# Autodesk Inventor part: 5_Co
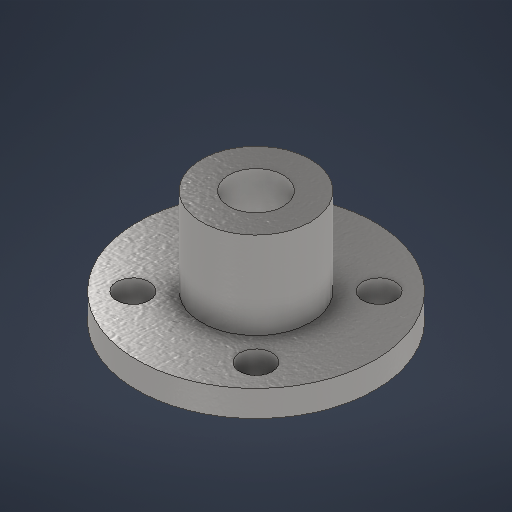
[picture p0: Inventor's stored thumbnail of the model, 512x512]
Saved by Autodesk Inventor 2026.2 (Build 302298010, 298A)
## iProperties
Created: 2026-03
Part Number: 5_Co
Material: 스테인리스스틸
Document SubType Name: Modeling
Designer: work
Density: 8 g/cm^3
Appearance: 아연도금
Mass: 10.0186 g
Surface Area: 13.3747 cm^2
Volume: 1.25232 cm^3
Author: work
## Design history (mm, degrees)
sketch "스케치1"
  geometry: L1 (0, 0)-(0, 10.4); L2 (2.5, 0)-(2.5, 10.4); L3 (2.5, 10.4)-(5, 10.4); L4 (5, 10.4)-(5, 2.4); L5 (5, 2.4)-(10.95, 2.4); L6 (10.95, 2.4)-(10.95, 0); L7 (2.5, 0)-(10.95, 0); L8 (2.5, 0)-(0, 0); 1 further point
  constraints: 16 end point, 6 perpendicular, 2 vertical, 1 midpoint
  dimensions: "d0" = 10.4 distance of L1.start L1.end; "d1" = 2.4 distance between parallel lines of L5 L7; "d2" = 10 diameter of L4 L1; "d3" = 5 diameter of L2 L1; "d4" = 10.4 distance from line of L1.start L3; "d5" = 21.9 diameter of point (10.95, 1.2) L1
revolve "회전1" sketch "스케치1" stored, may be unused: angle "d6" = 90 deg
sketch "스케치2"
  geometry: L1 (5.657, -5.657)-(-5.657, -5.657); L2 (-5.657, -5.657)-(-5.657, 5.657); L3 (-5.657, 5.657)-(5.657, 5.657); L4 (5.657, 5.657)-(5.657, -5.657); L5 (5.657, -5.657)-(-5.657, 5.657); L6 (-5.657, -5.657)-(5.657, 5.657); A1 r 8 centre (0, 0) between (-5.657, 5.657) and (5.657, -5.657); 4 further points
  constraints: 12 end point, 4 coincident, 2 midpoint, 2 parallel, 2 perpendicular, 2 point on circle, 1 centre point, 1 horizontal
  dimensions: "d7" = 16 diameter of A1
hole "구멍1" sketch "스케치2" at (-5.657, -5.657), (5.657, -5.657), (5.657, 5.657), (-5.657, 5.657) diameter "d8" = 3; stored, may be unused: countersink angle "d12" = 90 deg, drill point angle "d14" = 0 deg; dims "d9" = 6, "d10" = 4, "d11" = 2, "d13" = 3
sketch "스케치3"
  geometry: L1 (10.4, -2.5)-(10.4, 2.5) reference; L2 (10.4, 0)-(6.4, 0); C1 r 1 at (6.4, 0); 1 further point
  constraints: 2 end point, 1 centre point, 1 coincident, 1 horizontal, 1 midpoint
  dimensions: "d15" = 4 distance of L2.start L2.end; "d16" = 2 diameter of C1
extrude "돌출1" cut sketch "스케치3" distance "d17" = 10; taper "d18" = 0 deg
node "솔리드1"
feature "A9D066F2-1C7D-4E18-AEED-F7BC21143FA4" dims "d8" = 3, "d9" = 6, "d10" = 4, "d11" = 2, "d12" = 90 deg, "d13" = 3, "d14" = 0
